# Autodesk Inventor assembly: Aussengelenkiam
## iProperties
Created: 2005-01
Part Number: Aussengelenkiam
Document SubType Name: Assembly
Designer: Administrator
Manufacturer: Standard
Standards Organization: Custom
Author: Administrator
